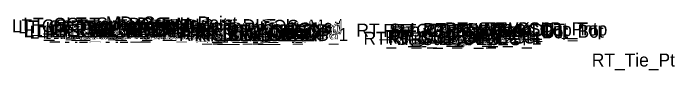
# Model space of a CAD drawing. Extents: x 0 to 4229, y -1 to 9523.
# Drawn here: x 2122.8 to 2224.5, y 508.6 to 516.9 of the extents above; entities that cross this region are included whole.
import ezdxf

# ---------------------------------------------------------------- set-up
doc = ezdxf.new("R2010")
doc.units = 0
doc.layers.add('Default', color=7, linetype='Continuous')

msp = doc.modelspace()

# ---------------------------------------------------------------- texts
at = {"layer": 'Default'}
for s, p in [('LT_CG_Top_BOC_Med', (2124.4, 514.64)), ('LT_Sub_DLT_In', (2131.01, 514.68)), ('MD_Crown Point', (2137.07, 514.84)), ('LT_CG_Top_Face_Med', (2122.62, 514.39)), ('LT_CG_Top_Gut_Med', (2123.6, 514.23)), ('LT_CG_Bot_BOC_Med', (2124.44, 513.64)), ('LT_CG_Bot_IE_Med', (2124.56, 513.65)), ('LT_PV2_OEEOP', (2127.81, 513.98)), ('LT_PV3_OEEOP', (2127.81, 513.73)), ('LT_PV2_IEEOP', (2128.45, 513.98)), ('LT_CG1_Shelf_In', (2128.68, 513.63)), ('LT_PV2_PGL', (2129.71, 513.98)), ('LT_PV1_PGL', (2130.28, 514.23)), ('RT_CG_Top_Face_Med', (2144.07, 514.07)), ('RT_CG_Top_BOC_Med', (2144.34, 514.32)), ('RT_CG_Top_Gut_Med', (2145.05, 513.91)), ('RT_Sub_DLT_In', (2146.82, 514.43)), ('RT_PV2_OEEOP', (2150.76, 513.64)), ('RT_PV2_IEEOP', (2151.41, 513.64)), ('RT_PV2_PGL', (2152.67, 513.64)), ('RT_PV1_PGL', (2153.23, 513.89)), ('RT_Sub_Trench_Out_DLT', (2175.59, 513.73)), ('RT_CG_Top_Face', (2179.71, 513.69)), ('RT_CG_Top_BOC', (2181.24, 513.69)), ('RT_SDWK_In_Top', (2185.81, 513.81)), ('RT_SDWK_Out_Top', (2189.19, 513.91)), ('RT_SDWK_Out_Bot', (2189.22, 513.57)), ('RT_CSLP_Pnt', (2195.13, 513.93)), ('LT_Sub_IEOT_CG_1', (2125.37, 513.4)), ('LT_Sub_OEEOP', (2127.71, 513.36)), ('LT_Sub_IEEOP', (2128.36, 513.36)), ('LT_Sub_PGL', (2129.62, 513.36)), ('LT_Sub_IEOP', (2131.52, 513.38)), ('RT_CG_Bot_BOC_Med', (2144.37, 513.34)), ('RT_CG_Bot_IE_Med', (2147.52, 513.31)), ('RT_CG1_Shelf_In', (2147.62, 513.35)), ('RT_Sub_IEOT_CG_1', (2148.32, 513.06)), ('RT_Sub_IEOP', (2149.95, 513.1)), ('RT_Sub_OEEOP', (2150.67, 513.02)), ('RT_PV3_OEEOP', (2150.76, 513.39)), ('RT_Sub_IEEOP', (2151.31, 513.02)), ('RT_Sub_PGL', (2152.57, 513.02)), ('RT_Sub_OEOT_CG_1', (2176.67, 512.48)), ('RT_CG1_Shelf_Out', (2180, 512.67)), ('RT_CG_Bot_IE', (2180.37, 512.73)), ('RT_Sub_OEOT', (2180.53, 512.44)), ('RT_PV2_OEOT', (2180.63, 513.06)), ('RT_PV3_OEOT', (2180.63, 512.81)), ('RT_CG_Top_Gut', (2180.69, 513.19)), ('RT_PV1_OEOT', (2181.19, 513.31)), ('RT_CG_Bot_BOC', (2181.27, 512.68)), ('RT_SDWK_In_Bot', (2185.84, 513.47)), ('RT_Sub_OEOP', (2183.82, 512.41)), ('RT_Tie_Pt', (2211.77, 509.14))]:
    msp.add_text(s, height=2, dxfattribs=at).set_placement(p)

doc.saveas('drawing.dxf')
